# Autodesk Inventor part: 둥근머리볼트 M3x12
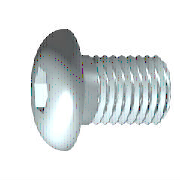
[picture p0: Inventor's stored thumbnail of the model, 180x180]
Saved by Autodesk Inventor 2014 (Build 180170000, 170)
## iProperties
IsCustomPart: 0
Created: 2012-02
Part Number: 둥근머리볼트 M3x12
Material: 강철
Description: 6각 소켓 버튼 머리 나사 - 제품 등급 A
Document SubType Name: Modeling
Standard: ISO 7380
Designer: mduedu
Standard Revision: Third edition 2004-01-15
Standards Organization: ISO
Language: ko-KR
Size Designation: M3 x 12
Categories: <MemberInstance><Categories><Category DisplayName="조임쇠" InternalName="e4da775c-781d-43d5-af7c-5136215cf5a6" Mnemonic="FSTN"><Category DisplayName="볼트" InternalN
Density: 7.85 g/cm^3
Appearance: 강철
Mass: 0.90169 g
Surface Area: 1.87531 cm^2
Volume: 0.114865 cm^3
Author: mduedu
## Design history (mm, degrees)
sketch "스케치1"
  geometry: L1 (0.057, 0)-(12, 0); L2 (12, 0)-(12, 1.5); L3 (12, 1.5)-(1, 1.5); L4 (1, 1.5)-(0.693, 1.5); L5 (0.693, 1.5)-(0, 1.5); L6 (0, 1.5)-(0, 2.85); L7 (0, 2.85)-(-1.65, 2.85); L8 (-1.65, 2.85)-(-1.65, 1.155); L9 (-1.65, 1.155)-(-0.61, 1.155); L10 (-0.61, 1.155)-(0.057, 0); L11 (-4.38, 0)-(14.73, 0) reference; L12 (0, -0.57)-(0, 3.42) reference; L13 (1, 1.5)-(0, 1.5)
  constraints: 22 end point, 6 parallel, 2 collinear, 2 perpendicular, 1 horizontal, 1 point on line
  dimensions: "d1" = 11 distance from line of L3.end L2 (= GEL); "d2" = 0.30683 distance of L4.end L3.end (computed from GAL); "d3" = 1.65 distance between parallel lines of L8 L6 (= KOH); "d4" = 1.04 distance of L8.end L9.end (= INTI); "d5" = 60 deg angle of L10 L1; "d6" = 3 diameter of L3 L1 (= GD); "d7" = 3 diameter of L5 L1 (= BDM); "d8" = 2.3094 diameter of L9 L1 (= 1.1547 x SW); "d9" = 5.7 diameter of L7 L1 (= KOD); "d26" = 12 distance between parallel lines of L12 L2 (= NLG)
revolve "본체" sketch "스케치1" stored, may be unused: angle "d10" = 90 deg
sketch "스케치2"
  geometry: L1 (0, -3.99)-(0, 3.99) reference; L2 (-3.99, 0)-(3.99, 0) reference; L3 (1.155, 0)-(0.577, -1); L4 (0.577, -1)-(-0.577, -1); L5 (-0.577, -1)-(-1.155, 0); L6 (-1.155, 0)-(-0.577, 1); L7 (-0.577, 1)-(0.577, 1); L8 (0.577, 1)-(1.155, 0); 2 further points
  constraints: 12 end point, 1 coincident, 1 horizontal alignment, 1 point on line, 12 other
extrude "슬롯" join sketch "스케치2" stored distance "d11" = 10; taper "d12" = 0 deg
workplane "Work Plane1"
body "Solid1"
fillet "모깎기1" dims "d17" = 1.45 (= RR)
feature "스레드" dims "d13" = 11 (= GEL), "d14" = 0
chamfer "모따기1" distance "d15" = 0.30673 (= -0.5 x SPD + 0.5 x GD); stored, may be unused: second distance "d16" = 0.30673 (= GUL), angle "d27" = 45 deg
fillet "모깎기2" dims "d30" = 0.1 (= R)
other parameters: "GD" = 3 (= NND) [user parameter; used in 2 equation terms], "NLG" = 12 [user parameter; used in 1 equation term], "GEL" = 11 [user parameter; used in 2 equation terms], "KOD" = 5.7 [user parameter; used in 1 equation term], "KOH" = 1.65 [user parameter; used in 1 equation term], "INTI" = 1.04 [user parameter; used in 1 equation term], "GAL" = 0.30673 (= 0.61345 x PTC) [user parameter; used in 1 equation term], "GUL" = 0.30673 (= 0.61345 x PTC) [user parameter; used in 1 equation term], "BDM" = 3 (= NND) [user parameter; used in 1 equation term], "SW" = 2 [user parameter; used in 1 equation term], "RR" = 1.45 [user parameter; used in 1 equation term], "SPD" = 2.38655 (= NND - 1.2269 x PTC) [user parameter; used in 1 equation term], "d19" = 0, "d28" = 0, "d29" = 0, "R" = 0.1 [user parameter; used in 1 equation term], "TOA" = 30 deg [user parameter], "GD1" = 2.38655 (= THREADDIA - 1.2269 x PTC) [user parameter], "THREADDIA" = 3 [user parameter; used in 1 equation term], "PTC" = 0.5 [user parameter; used in 5 equation terms], "NND" = 3 [user parameter; used in 3 equation terms], "KOH1" = 0.2 [user parameter], "E0" = 2.31 [user parameter]
